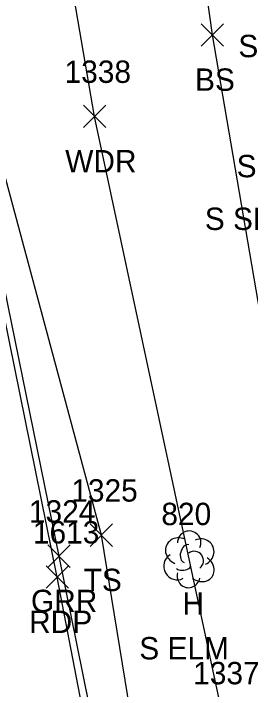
# Model space of a CAD drawing. Extents: x 1545627 to 1546562, y 571176 to 576667.
# Drawn here: x 1546104.7 to 1546125.9, y 572253.7 to 572314.1 of the extents above; entities that cross this region are included whole.
import ezdxf

# ---------------------------------------------------------------- set-up
doc = ezdxf.new("R2010")
doc.units = 0
for name, color, linetype in [('L_A', 7, 'Continuous'), ('L_C', 7, 'Continuous'), ('L_I', 7, 'Continuous'), ('L_TIC', 7, 'Continuous'), ('LAWA', 7, 'Continuous'), ('LELB', 7, 'Continuous'), ('LTD', 7, 'Continuous'), ('P_A', 7, 'Continuous'), ('P_I', 7, 'Continuous'), ('P_TIC', 7, 'Continuous'), ('PET', 7, 'Continuous'), ('R_A', 7, 'Continuous'), ('R_I', 7, 'Continuous'), ('R_TIC', 7, 'Continuous'), ('RGR', 7, 'Continuous')]:
    doc.layers.add(name, color=color, linetype=linetype)

msp = doc.modelspace()

# ---------------------------------------------------------------- linework, layer by layer
at = {"layer": 'L_TIC'}
for points in [[(1546121.485, 572311.188), (1546123.485, 572313.188)], [(1546123.485, 572311.188), (1546121.485, 572313.188)], [(1546110.937, 572303.897), (1546112.937, 572305.897)], [(1546112.937, 572303.897), (1546110.937, 572305.897)], [(1546111.539, 572266.479), (1546113.539, 572268.479)], [(1546113.539, 572266.479), (1546111.539, 572268.479)]]:
    msp.add_lwpolyline(points, dxfattribs=at)
at = {"layer": 'LAWA'}
msp.add_lwpolyline([(1546132.696, 572194.892), (1546123.453, 572251.154), (1546111.937, 572304.897), (1546099.961, 572374.277), (1546086.111, 572421.028), (1546079.849, 572451.625), (1546071.905, 572496.172), (1546064.394, 572527.582), (1546058.594, 572548.653), (1546052.091, 572585.928), (1546038.425, 572619.665), (1546027.83, 572654.921), (1546018.77, 572685.669), (1546005.342, 572728.46), (1545993.814, 572765.207), (1545980.931, 572799.992)], dxfattribs=at)
at = {"layer": 'LELB'}
for points in [[(1546125.533, 572192.436), (1546119.789, 572223.125), (1546112.539, 572267.479), (1546101.484, 572308.512), (1546092.302, 572354.824), (1546084.689, 572391.492), (1546079.385, 572418.936), (1546072.143, 572452.753), (1546063.265, 572495.373), (1546056.178, 572525.93), (1546052.452, 572548.057), (1546043.75, 572580.7), (1546033.096, 572617.265), (1546022.592, 572652.847), (1546012.21, 572685.195), (1545999.024, 572724.088), (1545985.45, 572763.438), (1545973.138, 572794.948)], [(1546138.092, 572206.647), (1546133.659, 572247.148), (1546122.485, 572312.188), (1546113.316, 572377.356), (1546104.81, 572426.631), (1546099.996, 572460.654), (1546092.988, 572497.654), (1546081.836, 572529.538), (1546071.729, 572550.604), (1546058.937, 572584.302), (1546058.009, 572591.614), (1546041.849, 572621.011), (1546036.285, 572644.955)]]:
    msp.add_lwpolyline(points, dxfattribs=at)
at = {"layer": 'LTD'}
msp.add_line((1546120.361, 572265.375), (1546120.361, 572265.375), dxfattribs=at)
msp.add_line((1546120.361, 572265.375), (1546120.361, 572265.375), dxfattribs=at)
msp.add_arc((1546120.408, 572266.809), 1.047, 335.52715, 180.95627, dxfattribs=at)
for centre, major_axis, ratio, start_param, end_param in [((1546119.569, 572266.041), (1.21, -0.512), 0.895232, 1.570796, 4.712389), ((1546121.402, 572265.958), (-1.141, -0.483), 0.949671, 1.570796, 4.712389), ((1546120.152, 572265.833), (-0.208, -0.792), 0.645439, 3.141593, 6.283185), ((1546120.861, 572265.208), (-0.5, 0.667), 0.989748, 3.141593, 6.283185), ((1546119.278, 572264.666), (0.584, -1.042), 0.959034, 3.141593, 6.283185), ((1546121.361, 572264.541), (-1.09, 0.792), 0.841452, 1.570796, 4.712389), ((1546119.903, 572264.625), (-0.625, -0.083), 0.423636, 0, 3.141593), ((1546120.361, 572263.875), (0.265, 1.061), 0.942809, 1.570796, 4.712389)]:
    msp.add_ellipse(centre, major_axis=major_axis, ratio=ratio, start_param=start_param, end_param=end_param, dxfattribs=at)
at = {"layer": 'P_TIC'}
for points in [[(1546107.582, 572262.735), (1546109.582, 572264.735)], [(1546109.582, 572262.735), (1546107.582, 572264.735)]]:
    msp.add_lwpolyline(points, dxfattribs=at)
at = {"layer": 'PET'}
msp.add_lwpolyline([(1546019.19, 572549.754), (1546028.198, 572511.711), (1546038.291, 572466.999), (1546043.906, 572438.712), (1546048.458, 572419.826), (1546059.016, 572375.225), (1546068.403, 572327.334), (1546078.966, 572280.941), (1546081.531, 572262.744), (1546083.99, 572253.102), (1546089.432, 572227.88), (1546096.04, 572198.55), (1546104.441, 572159.778), (1546113.192, 572174.919), (1546122.626, 572188.985), (1546117.061, 572219.813), (1546108.582, 572263.735), (1546099.519, 572308.129), (1546091.038, 572348.985), (1546082.958, 572388.468), (1546076.514, 572419.415), (1546067.661, 572461.142), (1546060.504, 572495.348), (1546051.115, 572536.864)], dxfattribs=at)
at = {"layer": 'R_TIC'}
for points in [[(1546107.745, 572264.603), (1546109.745, 572266.603)], [(1546109.745, 572264.603), (1546107.745, 572266.603)]]:
    msp.add_lwpolyline(points, dxfattribs=at)
at = {"layer": 'RGR'}
msp.add_lwpolyline([(1546122.896, 572190.91), (1546117.322, 572223.344), (1546108.745, 572265.603), (1546099.878, 572308.896), (1546090.289, 572354.448), (1546082.741, 572391.052), (1546076.806, 572419.122), (1546069.968, 572452.166), (1546060.892, 572495.215), (1546054.251, 572525.612), (1546048.911, 572547.317), (1546040.705, 572580.212), (1546030.582, 572616.088), (1546020.216, 572652.04), (1546009.859, 572685.101), (1545996.97, 572723.718), (1545983.077, 572762.484), (1545970.878, 572794.287)], dxfattribs=at)

# ---------------------------------------------------------------- texts
at = {"layer": 'L_A'}
for s, p in [('BS', (1546120.926, 572307.188)), ('WDR', (1546109.299, 572299.897)), ('TS', (1546110.948, 572262.479)), ('H', (1546119.794, 572260.375))]:
    msp.add_text(s, height=2, dxfattribs=at).set_placement(p)
at = {"layer": 'L_C'}
for s, p in [('S SPRUCE', (1546124.807, 572310.192)), ('S.ASH', (1546124.654, 572299.462)), ('S SPRUCE', (1546121.8, 572294.753)), ('S ELM', (1546115.936, 572256.375))]:
    msp.add_text(s, height=2, dxfattribs=at).set_placement(p)
at = {"layer": 'L_I'}
for s, p in [('1338', (1546109.244, 572307.897)), ('1325', (1546109.846, 572270.479)), ('820', (1546117.912, 572268.375)), ('1337', (1546120.76, 572254.154))]:
    msp.add_text(s, height=2, dxfattribs=at).set_placement(p)
at = {"layer": 'P_A'}
msp.add_text('RDP', height=2, dxfattribs=at).set_placement((1546106.07, 572258.735))
at = {"layer": 'P_I'}
msp.add_text('1613', height=2, dxfattribs=at).set_placement((1546106.409, 572266.735))
at = {"layer": 'R_A'}
msp.add_text('GRR', height=2, dxfattribs=at).set_placement((1546106.233, 572260.603))
at = {"layer": 'R_I'}
msp.add_text('1324', height=2, dxfattribs=at).set_placement((1546106.052, 572268.603))

doc.saveas('drawing.dxf')
